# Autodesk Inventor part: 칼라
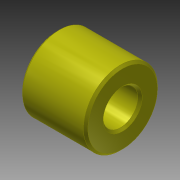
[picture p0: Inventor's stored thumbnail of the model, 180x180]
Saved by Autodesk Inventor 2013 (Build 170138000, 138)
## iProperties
Created: 2022-09
Part Number: 칼라
Material: 강철, 연강
Document SubType Name: Modeling
Designer: mdu-01
Density: 7.86 g/cm^3
Mass: 20.6803 g
Surface Area: 14.8552 cm^2
Volume: 2.63108 cm^3
Author: mdu-01
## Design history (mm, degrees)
sketch "스케치1"
  geometry: L1 (0, 0)-(15, 0); L2 (15, 0)-(15, 4); L3 (15, 8.5)-(0, 8.5); L4 (0, 8.5)-(0, 4); L5 (0, 4)-(15, 4); L6 (0, 4)-(0, 0); L7 (15, 4)-(15, 8.5); 1 further point
  constraints: 14 end point, 5 parallel, 4 perpendicular, 1 coincident, 1 horizontal
  dimensions: "d0" = 15 distance between parallel lines of L4 L2; "d2" = 17 diameter of L3 L1; "d3" = 8 diameter of L5 L1
revolve "회전1" sketch "스케치1" stored, may be unused: angle "d4" = 90 deg
chamfer "모따기1" distance "d5" = 0.5; stored, may be unused: second distance "d6" = 2, angle "d7" = 45 deg
node "솔리드1"
